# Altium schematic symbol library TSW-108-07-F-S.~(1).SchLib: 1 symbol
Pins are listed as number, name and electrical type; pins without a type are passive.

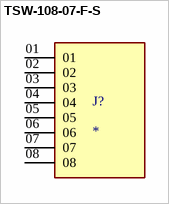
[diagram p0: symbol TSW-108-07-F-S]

## TSW-108-07-F-S
designator J?
MP: TSW-108-07-F-S; MF: Samtec
footprint SAMTEC_TSW-108-07-F-S
pins: 01, 02, 03, 04, 05, 06, 07, 08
